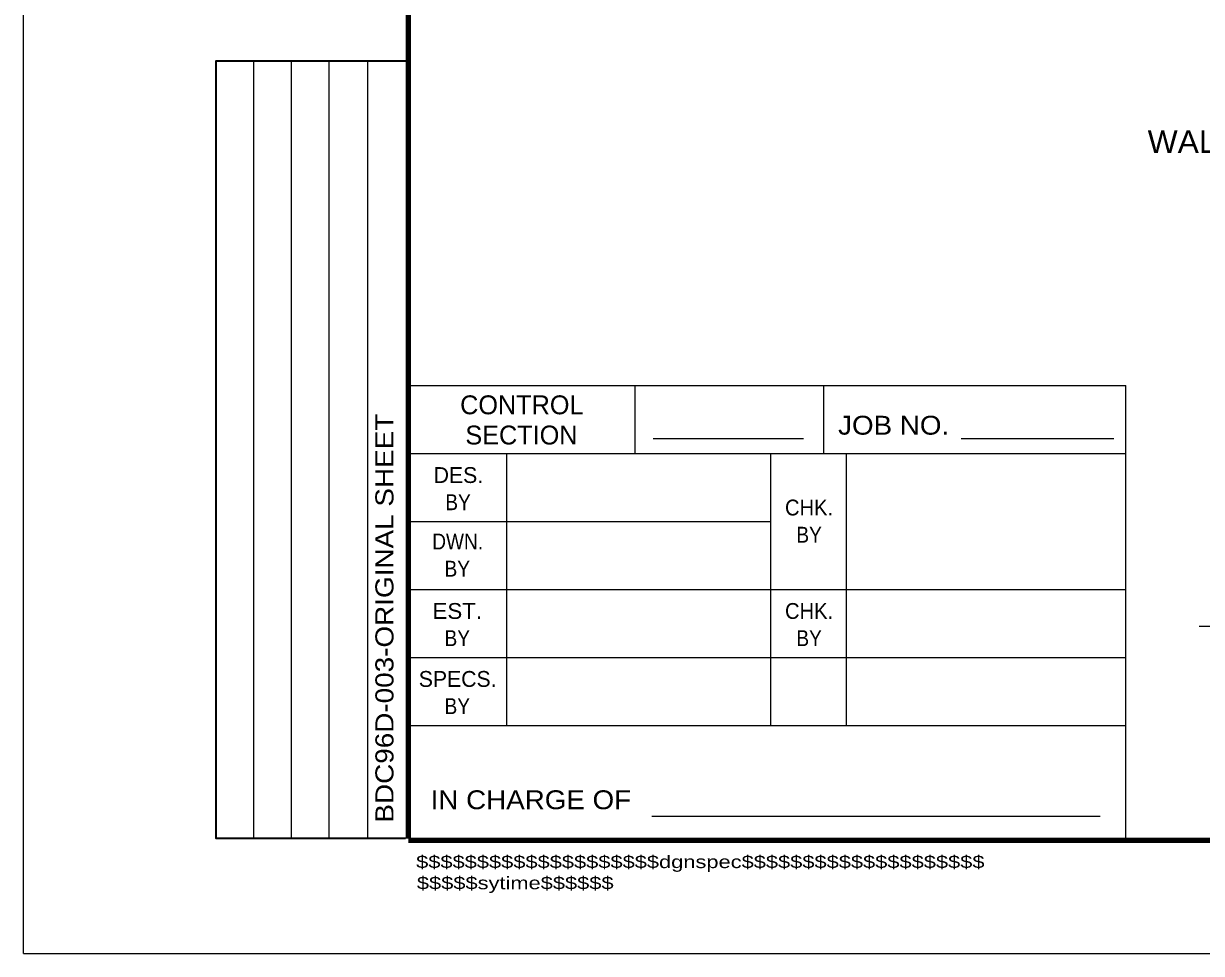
# Model space of a CAD drawing. Extents: x 312601.858 to 312602.699, y 144420.109 to 144420.704.
# Drawn here: x 312601.8578 to 312602.0138, y 144420.1095 to 144420.2326 of the extents above; entities that cross this region are included whole.
import ezdxf
from ezdxf.enums import TextEntityAlignment as Align

# ---------------------------------------------------------------- set-up
doc = ezdxf.new("R2010")
doc.units = 0
doc.header["$LTSCALE"] = 0.0012
for name, color, linetype, lineweight in [('1', 7, 'Continuous', 13), ('2', 7, 'Continuous', 13), ('39', 7, 'Continuous', 13), ('60', 7, 'Continuous', 25)]:
    doc.layers.add(name, color=color, linetype=linetype, lineweight=lineweight)

msp = doc.modelspace()

# ---------------------------------------------------------------- linework, layer by layer
at = {"layer": '1'}
msp.add_line((312602.0593, 144420.1528), (312602.0135, 144420.1528), dxfattribs=at)
at = {"layer": '39', "lineweight": 25}
for p, q in [((312601.8578, 144420.1095), (312601.8578, 144420.7035)), ((312601.9088, 144420.1847), (312602.0038, 144420.1847)), ((312602.0038, 144420.1247), (312602.0038, 144420.1847))]:
    msp.add_line(p, q, dxfattribs=at)
at = {"layer": '39'}
for p, q in [((312601.9088, 144420.1247), (312601.9088, 144420.1847)), ((312601.9388, 144420.1757), (312601.9388, 144420.1847)), ((312601.9638, 144420.1757), (312601.9638, 144420.1847)), ((312601.9412, 144420.1777), (312601.9611, 144420.1777)), ((312601.982, 144420.1777), (312602.0022, 144420.1777)), ((312601.9088, 144420.1757), (312602.0038, 144420.1757)), ((312601.9218, 144420.1397), (312601.9218, 144420.1757)), ((312601.9568, 144420.1397), (312601.9568, 144420.1757)), ((312601.9668, 144420.1397), (312601.9668, 144420.1757)), ((312601.9088, 144420.1667), (312601.9568, 144420.1667)), ((312601.9088, 144420.1577), (312602.0038, 144420.1577)), ((312601.9088, 144420.1487), (312602.0038, 144420.1487)), ((312601.9088, 144420.1397), (312602.0038, 144420.1397)), ((312601.941, 144420.1277), (312602.0004, 144420.1277)), ((312601.9088, 144420.1247), (312602.0038, 144420.1247))]:
    msp.add_line(p, q, dxfattribs=at)
at = {"layer": '39', "lineweight": 25}
msp.add_lwpolyline([(312601.8578, 144420.1095), (312602.6988, 144420.1095), (312602.6988, 144420.7035)], dxfattribs=at)
at = {"layer": '39', "lineweight": 158}
for points in [[(312601.9088, 144420.1245), (312602.6838, 144420.1245), (312602.6838, 144420.6645)], [(312601.9088, 144420.1247), (312601.9088, 144420.6645), (312602.6838, 144420.6645)]]:
    msp.add_lwpolyline(points, dxfattribs=at)
at = {"layer": '60'}
for p, q in [((312601.8883, 144420.1247), (312601.8883, 144420.2277)), ((312601.8933, 144420.1247), (312601.8933, 144420.2277)), ((312601.8983, 144420.1247), (312601.8983, 144420.2277)), ((312601.9034, 144420.1247), (312601.9034, 144420.2277))]:
    msp.add_line(p, q, dxfattribs=at)
at = {"layer": '60', "lineweight": 35}
msp.add_lwpolyline([(312601.9084, 144420.1247), (312601.8833, 144420.1247), (312601.8833, 144420.2277), (312601.9084, 144420.2277)], dxfattribs=at)

# ---------------------------------------------------------------- texts
at = {"layer": '1'}
for s, height, p in [('CONTROL', 0.0025, (312601.9238, 144420.1809)), ('SECTION', 0.0025, (312601.92375, 144420.1769)), ('DES.', 0.0021, (312601.9154, 144420.1718)), ('SPECS.', 0.0021, (312601.9153, 144420.1448))]:
    msp.add_text(s, height=height, dxfattribs=at).set_placement(p, align=Align.CENTER)
for s, height, width, p in [('JOB NO.', 0.0025, 1.1, (312601.97305, 144420.1782)), ('BY', 0.0021, 0.9, (312601.91535, 144420.1682)), ('CHK.', 0.0021, 0.95, (312601.96185, 144420.1675)), ('DWN.', 0.0021, 0.9, (312601.9153, 144420.163)), ('BY', 0.0021, 0.9, (312601.96185, 144420.1639)), ('BY', 0.0021, 0.9, (312601.91525, 144420.1594)), ('EST.', 0.0021, 1.05, (312601.91525, 144420.1538)), ('CHK.', 0.0021, 0.95, (312601.96185, 144420.1538)), ('BY', 0.0021, 0.9, (312601.91525, 144420.1502)), ('BY', 0.0021, 0.9, (312601.96185, 144420.1502)), ('BY', 0.0021, 0.9, (312601.91525, 144420.1412)), ('IN CHARGE OF', 0.0025, 1.1, (312601.925, 144420.1286))]:
    msp.add_text(s, height=height, dxfattribs=dict(at, width=width)).set_placement(p, align=Align.CENTER)
at = {"layer": '2'}
for s, height, width, p in [('WALKWAY GRATING', 0.003, 1.05, (312602.0067, 144420.2155)), ('$$$$$$$$$$$$$$$$$$$$dgnspec$$$$$$$$$$$$$$$$$$$$', 0.001664, 1.3, (312601.9098, 144420.1208)), ('$$$$$sytime$$$$$$', 0.001664, 1.3, (312601.9099, 144420.118))]:
    msp.add_text(s, height=height, dxfattribs=dict(at, width=width)).set_placement(p)
at = {"layer": '2', "width": 1.15}
msp.add_text('BDC96D-003-ORIGINAL SHEET', height=0.0024, rotation=90, dxfattribs=at).set_placement((312601.9068, 144420.1539), align=Align.CENTER)

doc.saveas('drawing.dxf')
